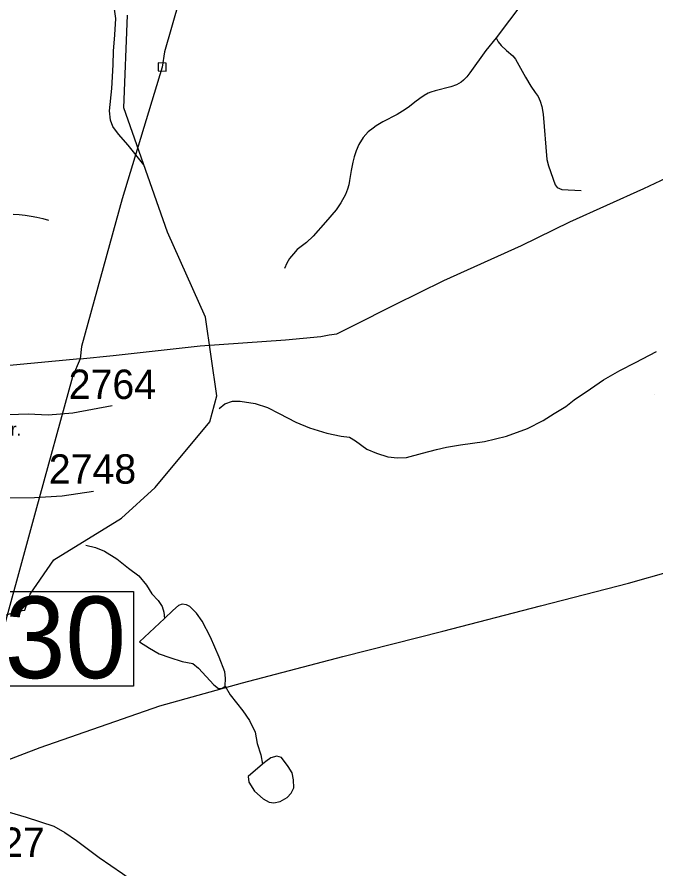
# Model space of a CAD drawing. Extents: x 1268485 to 1426702, y 514839 to 616766.
# Drawn here: x 1344690 to 1347900, y 536010 to 540290 of the extents above; entities that cross this region are included whole.
import ezdxf

# ---------------------------------------------------------------- set-up
doc = ezdxf.new("R2010")
doc.units = 0
for name, color, linetype in [('Old_Level_11', 7, 'Continuous'), ('Old_Level_21', 7, 'Continuous'), ('Old_Level_31', 7, 'Continuous'), ('Old_Level_32', 7, 'Continuous'), ('Old_Level_35', 7, 'Continuous'), ('Old_Level_56', 7, 'Continuous'), ('Old_Level_59', 7, 'Continuous'), ('Old_Level_62', 7, 'Continuous'), ('Old_Level_8', 7, 'Continuous')]:
    doc.layers.add(name, color=color, linetype=linetype)

msp = doc.modelspace()

# ---------------------------------------------------------------- linework, layer by layer
at = {"layer": 'Old_Level_21'}
msp.add_line((1347891.761, 538392.053), (1347891.761, 538392.053), dxfattribs=at)
at = {"layer": 'Old_Level_31'}
msp.add_lwpolyline([(1344572.794, 537403.146), (1345274.452, 537403.146), (1345274.452, 536928.006), (1344572.794, 536928.006), (1344572.794, 537403.146)], dxfattribs=at)
at = {"layer": 'Old_Level_32'}
for points in [[(1344028.939, 538072.108), (1344043.298, 538193.327), (1344059.3, 538232.143), (1344080.665, 538259.785), (1344118.055, 538277.061), (1344171.467, 538287.424), (1344251.587, 538292.607), (1344349.511, 538289.151), (1344548.921, 538289.151), (1344744.769, 538296.062), (1344846.254, 538290.879), (1344969.105, 538301.245), (1345166.734, 538337.525)], [(1343998.765, 537876.257), (1344370.877, 537867.619), (1344410.022, 537868.593), (1344648.625, 537874.527), (1344776.816, 537876.255), (1344915.692, 537884.893), (1345074.151, 537907.352)], [(1344438.534, 536340.416), (1344591.651, 536311.047), (1344735.867, 536269.585), (1344874.742, 536224.667), (1344929.935, 536193.57), (1344988.69, 536152.107), (1345102.638, 536067.454), (1345219.843, 535987.062), (1345316.052, 535918.701), (1345378.638, 535877.675), (1345444.483, 535837.684), (1345510.36, 535806.586), (1345576.236, 535784.127), (1345642.112, 535768.58), (1345763.182, 535749.575)]]:
    msp.add_lwpolyline(points, dxfattribs=at)
at = {"layer": 'Old_Level_35'}
for points in [[(1347359.51, 540535.747), (1347096.531, 540185.98), (1347044.653, 540121.337), (1346964.99, 540010.25), (1346949.406, 539990.206), (1346933.617, 539973.238), (1346921.724, 539963.241), (1346897.221, 539950.067), (1346869.744, 539940.02), (1346790.799, 539918.694), (1346768.14, 539911.825), (1346755.632, 539906.75), (1346734.922, 539896.139), (1346713.596, 539881.067), (1346688.478, 539862.253), (1346660.898, 539840.262), (1346639.675, 539825.857), (1346599.485, 539800.123), (1346528.024, 539763.726), (1346494.703, 539743.682), (1346479.119, 539732.353), (1346454.616, 539712.309), (1346429.497, 539684.063), (1346407.659, 539649.563), (1346393.715, 539618.241), (1346383.155, 539587.483), (1346376.286, 539561.134), (1346368.084, 539518.483), (1346359.984, 539468.297), (1346356.703, 539446.92), (1346349.834, 539424.365), (1346339.889, 539398.015), (1346317.231, 539357.262), (1346292.83, 539320.865), (1346239.003, 539259.452), (1346178.103, 539189.734), (1346144.269, 539157.182), (1346097.825, 539121.452), (1346078.345, 539100.742), (1346058.968, 539076.853), (1346044.511, 539053.067), (1346032.618, 539027.333)], [(1347096.531, 540185.98), (1347106.271, 540164.859), (1347121.343, 540146.815), (1347149.23, 540121.183), (1347180.09, 540095.5), (1347194.546, 540078.942), (1347244.989, 539988.515), (1347271.236, 539942.48), (1347292.356, 539911.568), (1347307.53, 539890.5), (1347317.987, 539867.124), (1347326.292, 539840.005), (1347332.341, 539801.507), (1347351.924, 539573.899), (1347359.51, 539542.167), (1347392.626, 539447.228), (1347403.084, 539433.694), (1347427.28, 539423.852), (1347524.475, 539418.572)], [(1344670.457, 539298.668), (1344700.498, 539297.232), (1344730.333, 539294.413), (1344759.963, 539290.26), (1344789.49, 539284.673), (1344818.71, 539277.804), (1344847.622, 539269.602)]]:
    msp.add_lwpolyline(points, dxfattribs=at)
at = {"layer": 'Old_Level_56'}
for points in [[(1348210.069, 550112.54), (1348169.999, 549921.255), (1348112.199, 549664.296), (1348033.556, 549365.936), (1347887.957, 548842.815), (1347749.887, 548385.575), (1347623.903, 547932.294), (1347430.598, 547246.056), (1346822.557, 545072.451), (1346515.911, 543964.491), (1346252.969, 543019.729), (1346237.442, 542944.205), (1346202.784, 542832.849), (1345973.91, 542069.489), (1345771.12, 541309.605), (1345580.378, 540641.322), (1345430.703, 540114.481), (1345418.971, 540038.681), (1345218.351, 539376.601), (1345013.922, 538634.757), (1345006.474, 538572.878)], [(1345398.568, 540019.083), (1345438.57, 540018.277), (1345439.376, 540058.28), (1345399.373, 540059.085), (1345398.568, 540019.083)], [(1345006.474, 538572.878), (1345172.882, 538589.338), (1345610.26, 538637.759), (1346039.075, 538668.345), (1346215.481, 538684.403), (1346257.885, 538693.554), (1346296.004, 538698.589), (1346372.814, 538737.063), (1346589.31, 538846.158), (1346834.055, 538966.891), (1347224.172, 539142.525), (1347466.872, 539261.098), (1347838.826, 539429.094), (1348152.135, 539576.26)], [(1345006.474, 538572.878), (1344968.423, 538481.8), (1344781.52, 537805.436), (1344576.972, 537057.592), (1344423.965, 536474.59)], [(1345006.474, 538572.878), (1344635.581, 538537.124)], [(1344423.965, 536474.59), (1344805.477, 536620.384), (1345406.359, 536829.193), (1345823.065, 536944.064), (1346326.178, 537077.205), (1346829.367, 537204.14), (1347320.355, 537331.322), (1347761.062, 537445.709), (1348187.89, 537566.378), (1348602.475, 537675.288), (1349101.829, 537810.504), (1349492.091, 537903.896), (1349894.715, 538015.047), (1350276.739, 538096.799), (1350570.474, 538166.322)]]:
    msp.add_lwpolyline(points, dxfattribs=at)
at = {"layer": 'Old_Level_59'}
for points in [[(1344629.77, 537285.193), (1344702.279, 537306.534), (1344728.18, 537309.201), (1344755.144, 537390.761), (1344875.099, 537562.287), (1345214.153, 537772.157), (1345384.141, 537926.306), (1345658.091, 538255.568), (1345694.077, 538386.135), (1345636.15, 538781.219), (1345445.144, 539208.445), (1345226.149, 539833.29), (1345244.091, 540299.066)], [(1345705.355, 538323.542), (1345733.96, 538346.765), (1345772.305, 538359.939), (1345810.239, 538359.171), (1345886.006, 538347.79), (1345947.624, 538328.515), (1346007.089, 538298.578), (1346090.033, 538255.055), (1346159.443, 538225.784), (1346246.898, 538199.383), (1346318.666, 538184.005), (1346360.599, 538179.032), (1346390.127, 538160.373), (1346447.234, 538119.055), (1346494.908, 538098.395), (1346552.425, 538080.812), (1346600.408, 538075.737), (1346646.442, 538076.455), (1346727.027, 538098.652), (1346797.463, 538117.722), (1346847.7, 538128.23), (1346918.033, 538140.739), (1347038.399, 538158.015), (1347149.025, 538183.697), (1347254.011, 538223.426), (1347332.854, 538262.027), (1347387.705, 538298.68), (1347446.453, 538333.642), (1347489.308, 538366.398), (1347570.509, 538422.224), (1347635.511, 538466.874), (1347718.659, 538513.626), (1347797.502, 538553.868), (1347902.796, 538609.18)]]:
    msp.add_lwpolyline(points, dxfattribs=at)
at = {"layer": 'Old_Level_62'}
for points in [[(1345180.422, 540200.179), (1345186.266, 540282.149), (1345177.551, 540340.589)], [(1345326.549, 539546.826), (1345248.294, 539646.538), (1345199.389, 539701.698), (1345170.374, 539740.042), (1345158.994, 539772.235), (1345153.97, 539818.321), (1345166.478, 539930.485), (1345173.143, 540050.133), (1345174.578, 540118.261), (1345180.422, 540200.179)], [(1345035.963, 537636.208), (1345083.637, 537624.572), (1345129.364, 537605.604), (1345190.572, 537568.233), (1345249.525, 537521.123), (1345300.685, 537482.316), (1345339.645, 537434.796), (1345366.712, 537392.401), (1345397.982, 537358.106), (1345419.41, 537328.937), (1345426.69, 537299.256), (1345430.073, 537268.857)], [(1345734.678, 536927.907), (1345737.549, 536968.046), (1345734.37, 537000.136), (1345705.97, 537074.519), (1345661.987, 537173.918), (1345619.849, 537255.17), (1345590.731, 537295.155), (1345557.41, 537328.63), (1345541.621, 537336.319), (1345519.578, 537340.882), (1345501.534, 537333.859), (1345472.929, 537308.176), (1345430.073, 537268.857)], [(1345430.073, 537268.857), (1345305.401, 537151.516), (1345354.716, 537118.554), (1345404.134, 537091.282), (1345457.652, 537072.161), (1345519.373, 537052.835), (1345573.097, 537041.916), (1345600.676, 537019.206), (1345678.904, 536935.597), (1345702.382, 536917.039), (1345718.376, 536916.732), (1345734.678, 536927.907)], [(1345734.678, 536927.907), (1345759.694, 536883.872), (1345823.978, 536803.799), (1345856.991, 536755.561), (1345885.699, 536696.711), (1345896.464, 536640.68), (1345915.226, 536583.727), (1345922.095, 536535.95)], [(1345922.095, 536535.95), (1345850.737, 536475.05), (1345854.121, 536445.42), (1345883.238, 536400.513), (1345926.299, 536361.912), (1345956.032, 536344.892), (1345980.023, 536342.791), (1346012.113, 536349.506), (1346046.562, 536369.345), (1346066.965, 536390.261), (1346079.678, 536417.891), (1346078.55, 536458.133), (1346071.271, 536492.735), (1346051.996, 536525.133), (1346018.88, 536570.142), (1345995.094, 536576.345), (1345964.951, 536568.758), (1345940.448, 536549.534), (1345922.095, 536535.95)]]:
    msp.add_lwpolyline(points, dxfattribs=at)

# ---------------------------------------------------------------- texts
at = {"layer": 'Old_Level_11'}
msp.add_text('Windwood Dr.', height=65.61666, dxfattribs=at).set_placement((1344160.16, 538185.998))
at = {"layer": 'Old_Level_31'}
msp.add_text('30', height=410.1042, dxfattribs=at).set_placement((1344627.516, 536968.462))
at = {"layer": 'Old_Level_8'}
for s, p in [('2764', (1344949.035, 538371.044)), ('2748', (1344849.072, 537945.476)), ('2827', (1344389.854, 536070.263))]:
    msp.add_text(s, height=147.6375, dxfattribs=at).set_placement(p)

doc.saveas('drawing.dxf')
